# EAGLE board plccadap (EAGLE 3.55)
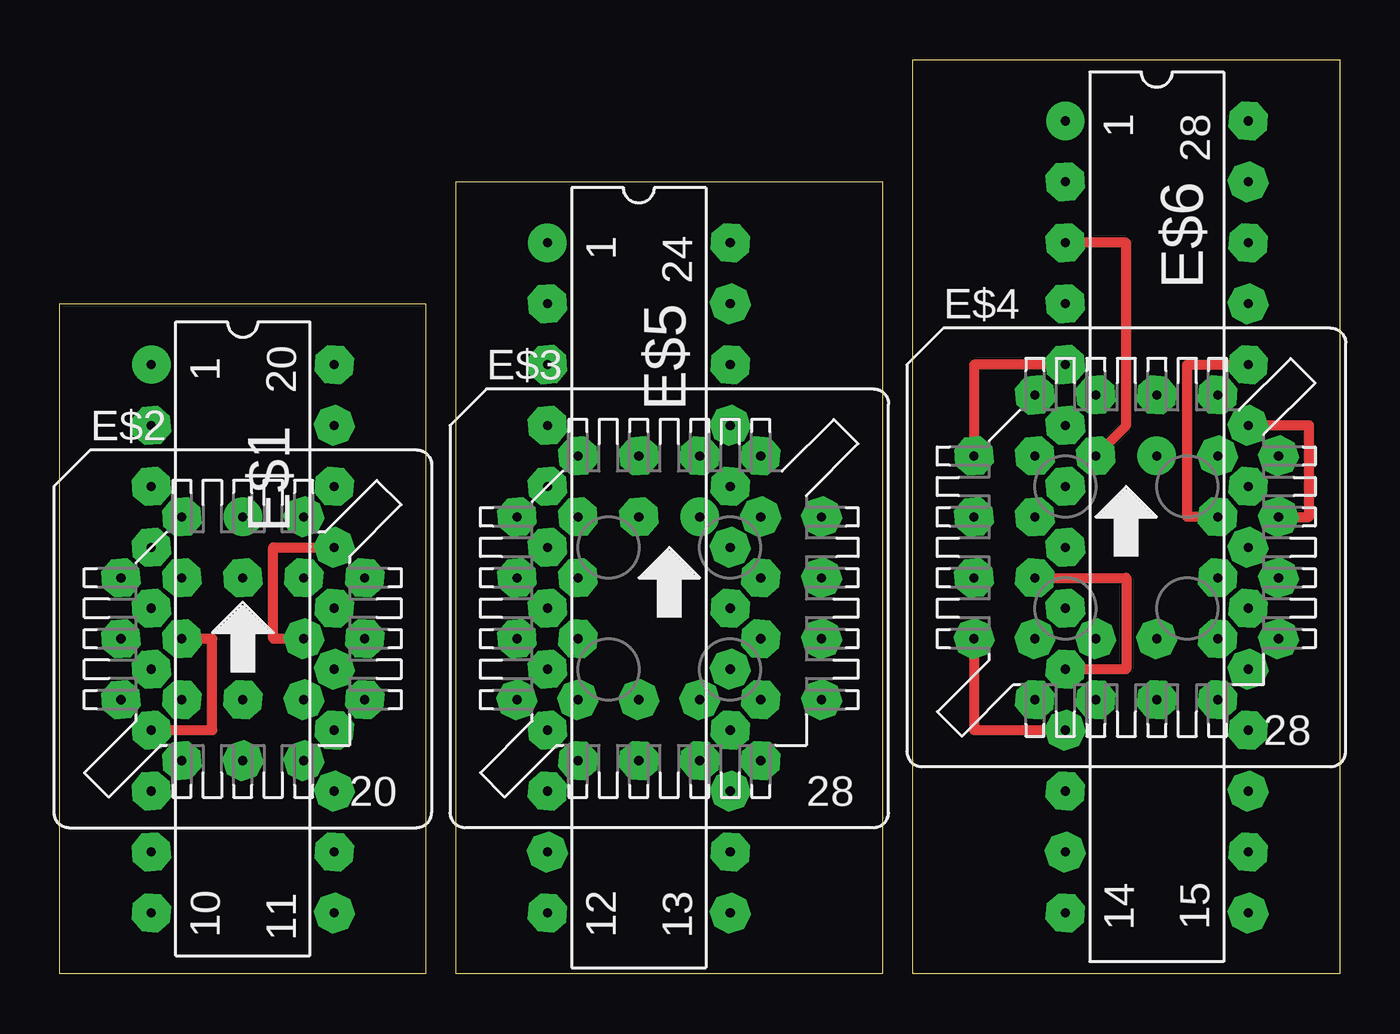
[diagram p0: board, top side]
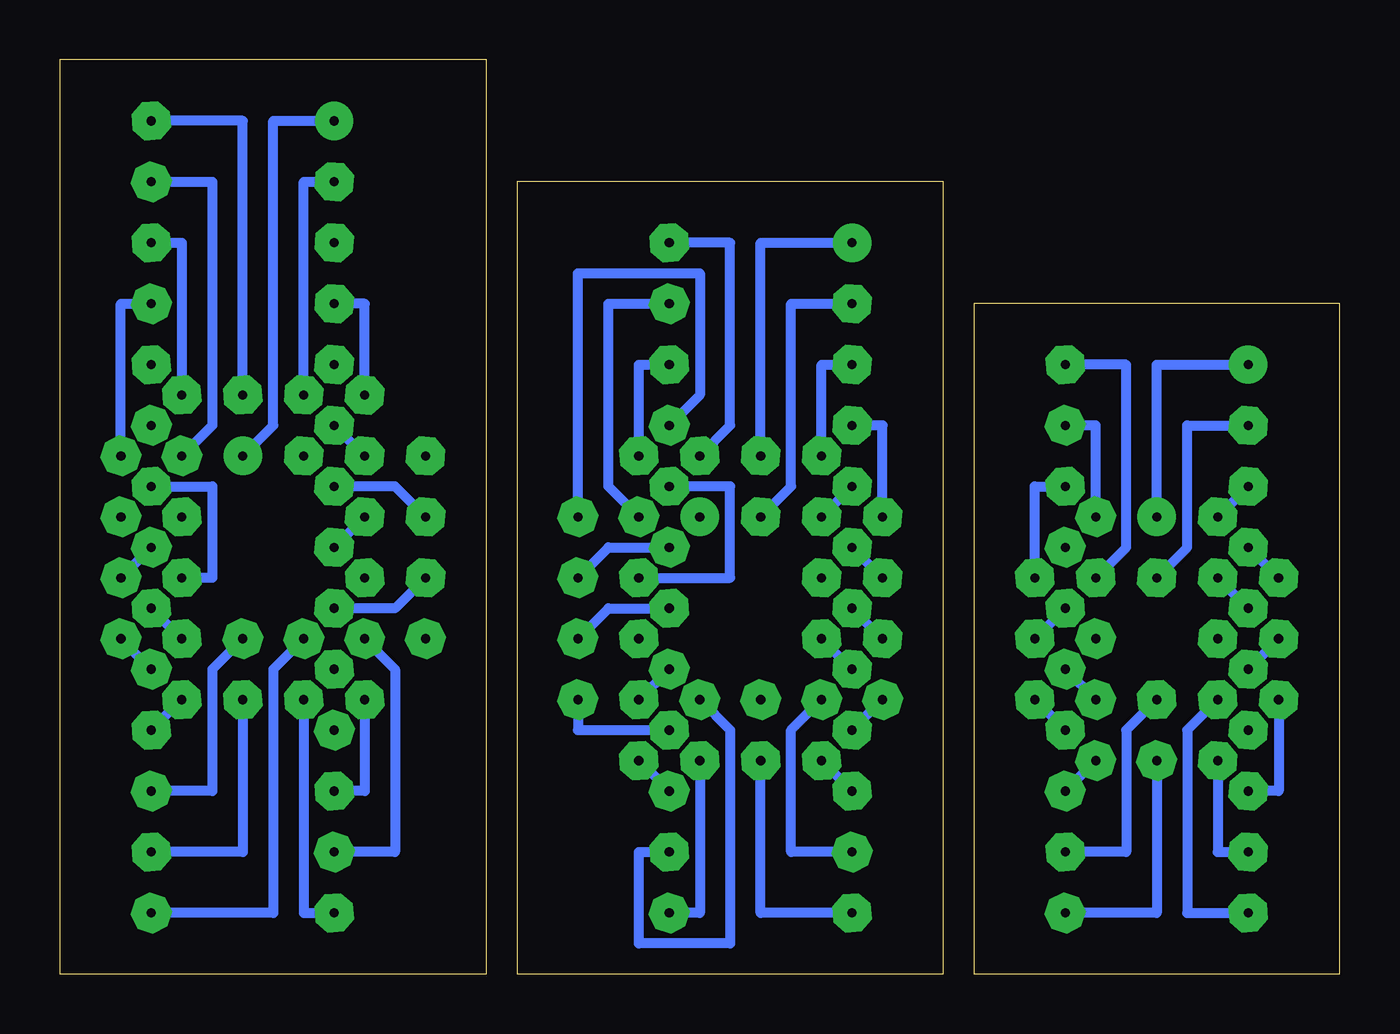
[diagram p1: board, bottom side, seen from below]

Size 53.34 x 38.1 mm. Coordinates in mm from the lower left corner, seen from the top.
Outline: 0,27.94 15.24,27.94 15.24,0 0,0 0,27.94
Outline: 16.51,33.02 34.29,33.02 34.29,0 16.51,0 16.51,33.02
Outline: 35.56,38.1 53.34,38.1 53.34,0 35.56,0 35.56,38.1
Copper layers used: Top, Bottom

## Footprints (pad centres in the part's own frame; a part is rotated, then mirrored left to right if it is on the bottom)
L20 = drill 0.381 pad 1.6 round:  -11.43,-3.81 | drill 0.381 pad 1.6 octagon:  -8.89,-3.81;  -6.35,-3.81;  -3.81,-3.81;  -1.27,-3.81;  1.27,-3.81;  3.81,-3.81;  6.35,-3.81;  8.89,-3.81;  11.43,-3.81;  11.43,3.81;  8.89,3.81;  6.35,3.81;  3.81,3.81;  1.27,3.81;  -1.27,3.81;  -3.81,3.81;  -6.35,3.81;  -8.89,3.81;  -11.43,3.81
0 = drill 0.381 pad 1.6 round:  0,5.08 | drill 0.381 pad 1.6 octagon:  0,2.54;  -2.54,5.08;  -5.08,2.54;  -2.54,2.54;  -5.08,0;  -2.54,0;  -5.08,-2.54;  -2.54,-5.08;  -2.54,-2.54;  0,-5.08;  0,-2.54;  2.54,-5.08;  5.08,-2.54;  2.54,-2.54;  5.08,0;  2.54,0;  5.08,2.54;  2.54,5.08;  2.54,2.54
8 = drill 0.381 pad 1.6 round:  1.27,3.81 | drill 0.381 pad 1.6 octagon:  -1.27,6.35;  -1.27,3.81;  -3.81,6.35;  -6.35,3.81;  -3.81,3.81;  -6.35,1.27;  -3.81,1.27;  -6.35,-1.27;  -3.81,-1.27;  -6.35,-3.81;  -3.81,-6.35;  -3.81,-3.81;  -1.27,-6.35;  -1.27,-3.81;  1.27,-6.35;  1.27,-3.81;  3.81,-6.35;  6.35,-3.81;  3.81,-3.81;  6.35,-1.27;  3.81,-1.27;  6.35,1.27;  3.81,1.27;  6.35,3.81;  3.81,6.35;  3.81,3.81;  1.27,6.35
L24-3 = drill 0.381 pad 1.6 round:  -13.97,-3.81 | drill 0.381 pad 1.6 octagon:  -11.43,-3.81;  -8.89,-3.81;  -6.35,-3.81;  -3.81,-3.81;  -1.27,-3.81;  1.27,-3.81;  3.81,-3.81;  6.35,-3.81;  8.89,-3.81;  11.43,-3.81;  13.97,-3.81;  13.97,3.81;  11.43,3.81;  8.89,3.81;  6.35,3.81;  3.81,3.81;  1.27,3.81;  -1.27,3.81;  -3.81,3.81;  -6.35,3.81;  -8.89,3.81;  -11.43,3.81;  -13.97,3.81
L28-3 = drill 0.381 pad 1.6 round:  -16.51,-3.81 | drill 0.381 pad 1.6 octagon:  -13.97,-3.81;  -11.43,-3.81;  -8.89,-3.81;  -6.35,-3.81;  -3.81,-3.81;  -1.27,-3.81;  1.27,-3.81;  3.81,-3.81;  6.35,-3.81;  8.89,-3.81;  11.43,-3.81;  13.97,-3.81;  16.51,-3.81;  16.51,3.81;  13.97,3.81;  11.43,3.81;  8.89,3.81;  6.35,3.81;  3.81,3.81;  1.27,3.81;  -1.27,3.81;  -3.81,3.81;  -6.35,3.81;  -8.89,3.81;  -11.43,3.81;  -13.97,3.81;  -16.51,3.81

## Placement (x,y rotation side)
E$1  [L20]  7.62,13.97 270 top
E$2  [0]  7.62,13.97 0 top
E$3  [8]  25.4,15.24 0 top
E$4  [8]  44.45,17.78 0 top
E$5  [L24-3]  24.13,16.51 270 top
E$6  [L28-3]  45.72,19.05 270 top

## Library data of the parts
E$1 E$5 E$6 = DIL
E$2-E$4 = PLCCPACK

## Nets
S$1: E$1. E$2.
S$2: E$1. E$2.
S$3: E$1. E$2.
S$4: E$1. E$2.
S$5: E$1. E$2.
S$6: E$1. E$2.
S$7: E$1. E$2.
S$8: E$4. E$6.
S$9: E$4. E$6.
S$10: E$1. E$2.
S$11: E$1. E$2.
S$12: E$1. E$2.
S$13: E$1. E$2.
S$14: E$1. E$2.
S$15: E$1. E$2.
S$16: E$1. E$2.
S$17: E$1. E$2.
S$18: E$1. E$2.
S$19: E$1. E$2.
S$20: E$1. E$2.
S$21: E$1. E$2.
S$22: E$1. E$2.
S$24: E$4. E$6.
S$25: E$4. E$6.
S$26: E$4. E$6.
S$27: E$4. E$6.
S$28: E$4. E$6.
S$29: E$4. E$6.
S$30: E$4. E$6.
S$31: E$4. E$6.
S$32: E$4. E$6.
S$33: E$4. E$6.
S$34: E$4. E$6.
S$35: E$4. E$6.
S$36: E$4. E$6.
S$37: E$4. E$6.
S$38: E$4. E$6.
S$39: E$4. E$6.
S$40: E$4. E$6.
S$41: E$4. E$6.
S$42: E$3. E$5.
S$43: E$3. E$5.
S$44: E$3. E$5.
S$45: E$3. E$5.
S$46: E$3. E$5.
S$47: E$3. E$5.
S$48: E$3. E$5.
S$49: E$3. E$5.
S$50: E$3. E$5.
S$51: E$3. E$5.
S$52: E$3. E$5.
S$53: E$3. E$5.
S$54: E$3. E$5.
S$55: E$3. E$5.
S$56: E$3. E$5.
S$57: E$3. E$5.
S$58: E$3. E$5.
S$59: E$3. E$5.
S$60: E$3. E$5.
S$61: E$3. E$5.
S$62: E$3. E$5.
S$63: E$3. E$5.
S$64: E$3. E$5.
S$65: E$3. E$5.
S$66: E$4. E$6.
S$67: E$4. E$6.
S$68: E$4. E$6.
S$69: E$4. E$6.
S$70: E$4. E$6.
S$71: E$4. E$6.
S$72: E$4. E$6.
S$73: E$4. E$6.

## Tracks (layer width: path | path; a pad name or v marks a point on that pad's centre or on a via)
S$1
  Bottom 0.406: 7.62,19.05 7.62,25.4 3.81,25.4
S$2
  Bottom 0.406: 7.62,16.51 6.35,17.78 6.35,22.86 3.81,22.86
S$3
  Bottom 0.406: 5.08,19.05 3.81,20.32
S$4
  Bottom 0.406: 2.54,16.51 3.81,17.78
S$5
  Bottom 0.406: 5.08,16.51 3.81,15.24
S$6
  Bottom 0.406: 2.54,13.97 3.81,12.7
S$7
  Bottom 0.406: 2.54,11.43 2.54,7.62 3.81,7.62
S$8
  Bottom 0.406: 45.72,21.59 44.45,22.86 44.45,35.56 41.91,35.56
S$9
  Bottom 0.406: 43.18,24.13 43.18,33.02 41.91,33.02
S$10
  Bottom 0.406: 7.62,8.89 7.62,2.54 11.43,2.54
S$11
  Bottom 0.406: 7.62,11.43 8.89,10.16 8.89,5.08 11.43,5.08
S$12
  Bottom 0.406: 10.16,8.89 11.43,7.62
S$13
  Bottom 0.406: 11.43,10.16 12.7,11.43
S$14
  Bottom 0.406: 11.43,12.7 10.16,11.43
S$15
  Bottom 0.406: 11.43,15.24 12.7,13.97
S$16
  Bottom 0.406: 12.7,16.51 12.7,20.32 11.43,20.32
S$17
  Bottom 0.406: E$2. 8.89,17.78 8.89,25.4 E$1.
S$18
  Bottom 0.406: 10.16,19.05 10.16,22.86 11.43,22.86
S$19
  Bottom 0.406: 5.08,8.89 5.08,5.08 3.81,5.08
S$20
  Bottom 0.406: 5.08,11.43 6.35,10.16 6.35,2.54 3.81,2.54
S$21
  Top 0.406: 3.81,10.16 6.35,10.16 6.35,13.97 5.08,13.97
S$22
  Top 0.406: 10.16,13.97 8.89,13.97 8.89,17.78 11.43,17.78
S$23
  Bottom 0: 0,27.94 15.24,27.94 15.24,0 0,0 0,27.94
S$24
  Bottom 0.406: 40.64,24.13 40.64,27.94 41.91,27.94
S$25
  Bottom 0.406: 40.64,21.59 41.91,22.86
S$26
  Bottom 0.406: 38.1,19.05 39.37,20.32 41.91,20.32
S$27
  Bottom 0.406: 40.64,19.05 41.91,17.78
S$28
  Bottom 0.406: 38.1,16.51 39.37,15.24 41.91,15.24
S$29
  Top 0.406: 38.1,13.97 38.1,10.16 41.91,10.16
S$30
  Bottom 0.406: 40.64,11.43 40.64,7.62 41.91,7.62
S$31
  Bottom 0.406: 40.64,13.97 39.37,12.7 39.37,5.08 41.91,5.08
S$32
  Bottom 0.406: 43.18,11.43 43.18,2.54 41.91,2.54
S$33
  Bottom 0.406: 43.18,13.97 44.45,12.7 44.45,2.54 49.53,2.54
S$34
  Bottom 0.406: 45.72,11.43 45.72,5.08 49.53,5.08
S$35
  Bottom 0.406: 45.72,13.97 46.99,12.7 46.99,7.62 49.53,7.62
S$36
  Bottom 0.406: 48.26,11.43 49.53,10.16
S$37
  Bottom 0.406: 48.26,13.97 49.53,15.24
S$38
  Bottom 0.406: 50.8,13.97 49.53,12.7
S$39
  Bottom 0.406: 49.53,33.02 46.99,33.02 46.99,22.86 48.26,21.59
S$40
  Bottom 0.406: 49.53,30.48 48.26,30.48 48.26,24.13
S$41
  Bottom 0.406: E$4. 45.72,35.56 E$6.
S$42
  Bottom 0.406: 24.13,21.59 24.13,30.48 20.32,30.48
S$43
  Bottom 0.406: 24.13,19.05 22.86,20.32 22.86,27.94 20.32,27.94
S$44
  Bottom 0.406: 21.59,21.59 21.59,25.4 20.32,25.4
S$45
  Bottom 0.406: 19.05,19.05 19.05,22.86 20.32,22.86
S$46
  Bottom 0.406: 21.59,19.05 20.32,20.32
S$47
  Bottom 0.406: 19.05,16.51 20.32,17.78
S$48
  Bottom 0.406: 26.67,8.89 26.67,2.54 27.94,2.54
S$49
  Bottom 0.406: 29.21,8.89 27.94,7.62
S$50
  Bottom 0.406: 31.75,11.43 31.75,10.16 27.94,10.16
S$51
  Bottom 0.406: 29.21,11.43 27.94,12.7
S$52
  Bottom 0.406: 31.75,13.97 30.48,15.24 27.94,15.24
S$53
  Bottom 0.406: 19.05,13.97 20.32,15.24
S$54
  Bottom 0.406: 20.32,12.7 21.59,13.97
S$55
  Bottom 0.406: 19.05,11.43 20.32,10.16
S$56
  Bottom 0.406: 20.32,7.62 21.59,8.89
S$57
  Bottom 0.406: 20.32,5.08 22.86,5.08 22.86,10.16 21.59,11.43
S$58
  Bottom 0.406: 20.32,2.54 24.13,2.54 24.13,8.89
S$59
  Bottom 0.406: E$3. 25.4,22.86 25.4,30.48 E$5.
S$60
  Bottom 0.406: 29.21,19.05 30.48,20.32 30.48,27.94 27.94,27.94
S$61
  Bottom 0.406: 29.21,21.59 29.21,25.4 27.94,25.4
S$62
  Bottom 0.406: 26.67,11.43 25.4,10.16 25.4,1.27 29.21,1.27 29.21,5.08 27.94,5.08
S$63
  Bottom 0.406: 31.75,16.51 30.48,17.78 27.94,17.78
S$64
  Bottom 0.406: 29.21,16.51 25.4,16.51 25.4,20.32 27.94,20.32
S$65
  Bottom 0.406: 31.75,19.05 31.75,29.21 26.67,29.21 26.67,24.13 27.94,22.86
S$66
  Top 0.406: 43.18,21.59 44.45,22.86 44.45,30.48 41.91,30.48
S$67
  Top 0.406: 41.91,25.4 38.1,25.4 38.1,21.59
S$68
  Top 0.406: 40.64,16.51 44.45,16.51 44.45,12.7 41.91,12.7
S$69
  Bottom 0.406: 50.8,16.51 49.53,17.78
S$70
  Bottom 0.406: 49.53,20.32 46.99,20.32 46.99,16.51 48.26,16.51
S$71
  Bottom 0.406: 50.8,21.59 50.8,27.94 49.53,27.94
S$72
  Top 0.406: 50.8,19.05 52.07,19.05 52.07,22.86 49.53,22.86
S$73
  Top 0.406: 48.26,19.05 46.99,19.05 46.99,25.4 49.53,25.4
